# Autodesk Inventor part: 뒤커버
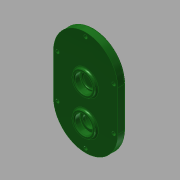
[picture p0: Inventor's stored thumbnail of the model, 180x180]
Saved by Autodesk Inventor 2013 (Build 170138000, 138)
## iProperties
Created: 2016-12
Part Number: 뒤커버
Material: 일반
Document SubType Name: Modeling
Designer: mduedu
Density: 1 g/cm^3
Author: mduedu
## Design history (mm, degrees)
sketch "스케치1"
  geometry: L1 (40, -25)-(40, 25); L2 (-40, 25)-(-40, -25); L3 (-40, -25)-(40, 25); L4 (40, -25)-(-40, 25); A1 r 40 centre (0, 25) between (40, 25) and (-40, 25); A2 r 40 centre (0, -25) between (-40, -25) and (40, -25); 1 further point
  constraints: 8 end point, 4 point on circle, 4 tangent, 2 centre point, 2 midpoint, 1 parallel, 1 vertical
  dimensions: "d0" = 130 dimension on A2 A1; "d2" = 80 distance between parallel lines of L1 L2
extrude "돌출1" new body sketch "스케치1" distance "d3" = 10; taper "d4" = 0 deg
sketch "스케치2"
  geometry: C1 r 14 at (0, 11); 1 further point
  constraints: 1 centre point, 1 vertical alignment
  dimensions: "d5" = 28 diameter of C1; "d6" = 11 distance of C1.centre point (0, 0)
extrude "돌출2" join sketch "스케치2" distance "d7" = 3; taper "d8" = 0 deg
sketch "스케치3"
  geometry: C1 r 14 at (0, -33.1); C2 r 14 at (0, 11) reference; 1 further point
  constraints: 1 centre point, 1 vertical alignment
  dimensions: "d9" = 28 diameter of C1; "d69" = 44.1 distance of C1.centre C2.centre
extrude "돌출3" join sketch "스케치3" distance "d11" = 3; taper "d12" = 0 deg
hole "구멍1" diameter "d15" = 22; stored, may be unused: countersink angle "d19" = 90 deg, drill point angle "d21" = 0 deg; dims "d13" = 10, "d14" = 10, "d16" = 6, "d17" = 4, "d18" = 2, "d20" = 7
hole "구멍2" diameter "d24" = 18; stored, may be unused: countersink angle "d28" = 90 deg, drill point angle "d30" = 0 deg; dims "d22" = 10, "d23" = 10, "d25" = 6, "d26" = 4, "d27" = 2, "d29" = 1
hole "구멍3" diameter "d33" = 22; stored, may be unused: countersink angle "d37" = 90 deg, drill point angle "d39" = 0 deg; dims "d31" = 10, "d32" = 10, "d34" = 6, "d35" = 4, "d36" = 2, "d38" = 7
sketch "스케치4"
  geometry: C1 r 14 at (0, -33.1) reference; C2 r 18 at (0, -33.1); 1 further point
  constraints: 1 centre point, 1 coincident
  dimensions: "d40" = 36 diameter of C2
extrude "돌출4" join sketch "스케치4" distance "d41" = 4; taper "d42" = 0 deg
hole "구멍4" diameter "d45" = 22; stored, may be unused: countersink angle "d49" = 90 deg, drill point angle "d51" = 0 deg; dims "d43" = 10, "d44" = 10, "d46" = 6, "d47" = 4, "d48" = 2, "d50" = 7
hole "구멍5" diameter "d54" = 15; stored, may be unused: countersink angle "d58" = 90 deg, drill point angle "d60" = 0 deg; dims "d52" = 10, "d53" = 10, "d55" = 6, "d56" = 4, "d57" = 2, "d59" = 7
fillet "모깎기1" dims "d61" = 0.3
fillet "모깎기2" dims "d62" = 2
chamfer "모따기1" distance "d63" = 1; stored, may be unused: second distance "d64" = 2, angle "d65" = 45 deg
fillet "모깎기3" dims "d66" = 2
fillet "모깎기4" dims "d67" = 2
fillet "모깎기5" dims "d68" = 2
sketch "스케치5"
  geometry: L1 (-40, 25)-(-40, -25) reference; L2 (40, -25)-(40, 25) reference; L3 (35, 25)-(35, -25); L4 (-35, -25)-(-35, 25); A1 r 40 centre (0, 25) between (40, 25) and (-40, 25) reference; A2 r 40 centre (0, -25) between (-40, -25) and (40, -25) reference; A3 r 35 centre (0, 25) between (35, 25) and (-35, 25); A4 r 35 centre (0, -25) between (-35, -25) and (35, -25); 2 further points
  constraints: 5 point on circle, 4 end point, 2 centre point, 1 vertical alignment, 3 other
  dimensions: "d70" = 5 distance between parallel lines of L2 L3
sketch "스케치6"
  geometry: 1 further point
hole "구멍6" sketch "스케치6" at (0, 60) diameter "d71" = 4.5; stored, may be unused: countersink angle "d75" = 90 deg, drill point angle "d77" = 0 deg; dims "d72" = 6, "d73" = 8, "d74" = 4.6, "d76" = 8
node "솔리드1"
pattern_linear "직사각형 패턴1"
